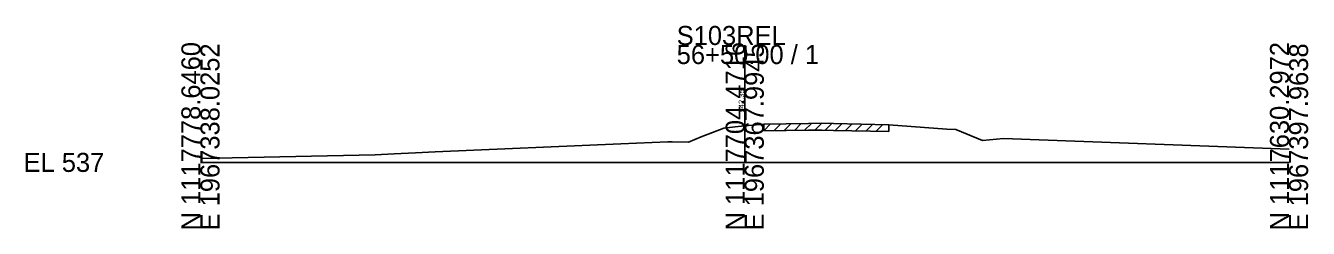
# Model space of a CAD drawing. Extents: x -26 to 163, y -10 to 24518.
# Drawn here: x -25.7 to 162.8, y 6990.3 to 7020.1 of the extents above; entities that cross this region are included whole.
import ezdxf

# ---------------------------------------------------------------- set-up
doc = ezdxf.new("R2010")
doc.units = 0
for name, color, linetype in [('RD_GPK_XS_Cell', 7, 'Continuous'), ('RD_XS_ExGround', 7, 'Continuous'), ('RD_XS_ExPaveRet', 7, 'Continuous'), ('RD_XS_TX_Elev_EX', 7, 'Continuous')]:
    doc.layers.add(name, color=color, linetype=linetype)

msp = doc.modelspace()

# ---------------------------------------------------------------- linework, layer by layer
at = {"layer": 'RD_GPK_XS_Cell'}
for p, q in [((80, 7000), (80, 7017.25)), ((0, 7000), (80, 7000)), ((80, 7000), (160, 7000))]:
    msp.add_line(p, q, dxfattribs=at)
at = {"layer": 'RD_XS_ExGround'}
msp.add_lwpolyline([(0, 7000.56), (25.66, 7001.12), (28.48, 7001.24), (31.63, 7001.38), (34.49, 7001.55), (61.79, 7002.72), (68.72, 7003.02), (69.32, 7003.01), (71.73, 7002.95), (73.61, 7003.74), (76.94, 7005.03), (79.03, 7005.25), (80, 7005.35), (82.8, 7005.64), (89.38, 7005.73), (91.31, 7005.75), (93.07, 7005.71), (101.2, 7005.52), (109.71, 7004.9), (111.05, 7004.81), (114.97, 7003.24), (118.01, 7003.49), (160, 7001.94)], dxfattribs=at)
at = {"layer": 'RD_XS_ExPaveRet'}
for p, q in [((82.8, 7004.64), (83.81, 7005.66)), ((82.8, 7004.64), (82.8, 7005.64)), ((82.8, 7004.64), (89.38, 7004.73)), ((84.3, 7004.66), (85.31, 7005.68)), ((85.8, 7004.68), (86.81, 7005.7)), ((87.3, 7004.7), (88.31, 7005.72)), ((88.8, 7004.72), (89.81, 7005.73)), ((89.38, 7004.73), (91.31, 7004.75)), ((90.3, 7004.74), (91.31, 7005.75)), ((91.31, 7004.75), (93.07, 7004.71)), ((91.8, 7004.74), (92.78, 7005.72)), ((93.07, 7004.71), (101.2, 7004.52)), ((93.3, 7004.71), (94.27, 7005.68)), ((94.8, 7004.67), (95.77, 7005.65)), ((96.3, 7004.64), (97.27, 7005.61)), ((97.8, 7004.6), (98.77, 7005.58)), ((99.3, 7004.57), (100.27, 7005.54)), ((101.2, 7005.52), (101.2, 7004.52))]:
    msp.add_line(p, q, dxfattribs=at)

# ---------------------------------------------------------------- texts
at = {"layer": 'RD_GPK_XS_Cell'}
for s, p in [('S103REL', (70, 7017.25)), ('56+50.00 / 1', (70, 7014.45)), ('EL 537', (-26, 6998.6))]:
    msp.add_text(s, height=2.8, dxfattribs=at).set_placement(p)
for s, p in [('N 1117778.6460', (0, 6990)), ('E 1967338.0252', (2.8, 6990)), ('N 1117704.4716', (80, 6990)), ('E 1967367.9945', (82.8, 6990)), ('N 1117630.2972', (160, 6990)), ('E 1967397.9638', (162.8, 6990))]:
    msp.add_text(s, height=2.8, rotation=90, dxfattribs=at).set_placement(p)
at = {"layer": 'RD_XS_TX_Elev_EX'}
msp.add_text('542.35', height=0.8, rotation=90, dxfattribs=at).set_placement((79.9, 7007.35))

doc.saveas('drawing.dxf')
